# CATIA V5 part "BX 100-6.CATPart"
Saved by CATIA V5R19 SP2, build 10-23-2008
Part number: BX 100-6
Bounding box of the stored display mesh (mm): x -18.951 to 18.951, y -18.952 to 18.952, z 0 to 61
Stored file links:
  C:\Users\Bora\Desktop\3D Katı model\BX serisi\BX 100\BX 100-6.CATPart
  C:\Program Files\Dassault Systemes\B19\intel_a\reffiles\standard\MetricThickPitch.txt
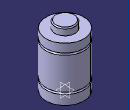
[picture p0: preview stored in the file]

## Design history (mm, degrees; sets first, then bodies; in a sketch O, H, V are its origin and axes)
Body1 (main body)
  Sketch1 on yz-plane, origin (0, 0, 0), H (0, 1, 0), V (0, 0, 1)
    point P1 (19, 45.5)
    line L1 (19, 54) -> (19, 45.5)
    point P4 (10, 60)
    line L2 (10, 60) -> (10, 54)
    point P6 (10, 60)
    arc A1 centre (9, 60) radius 1 from (10, 60) to (9, 61) ccw
    point P7 (19, 43.5)
    point P8 (19, 45.5)
    arc A2 centre (19, 44.5) radius 1 from (19, 45.5) to (19, 43.5) ccw
    point P9 (19, 11.5)
    point P10 (19, 43.5)
    line L3 (19, 43.5) -> (19, 11.5)
    point P11 (19, 9.5)
    point P12 (19, 11.5)
    arc A3 centre (19, 10.5) radius 1 from (19, 11.5) to (19, 9.5) ccw
    point P14 (19, 9.5)
    line L4 (19, 9.5) -> (19, 0)
    line L5 (9, 61) -> (0, 61)
    line L6 (10, 54) -> (19, 54)
    line L7 (19, 0) -> (0, 0)
    tangency: L5 A1
    horizontal: L6 H, L7 H
    coincidence: P1 P8, P4 P6, P7 P10, P9 P12, P11 P14
  Shaft1: profile Sketch1, axis Sketch1.V, angle 360
  Sketch2 on face of Shaft1 from Sketch1.L7, origin (0, 0, 0), H (1, 0, 0), V (0, -1, 0)
    point P1 (9, 0)
    distance P1 V = 9
  Hole1: placed by Sketch2, at (9, 0, 0) direction (0, 0, 1), diameter 4.917, depth 6, threaded "M6", thread diameter 6, thread depth 6, pitch 1
  Sketch3 on face of Shaft1 from Sketch1.L7, origin (0, 0, 0), H (1, 0, 0), V (0, -1, 0)
    point P1 (-9, 0)
    distance P1 V = 9
  Hole2: placed by Sketch3, at (-9, 0, 0) direction (0, 0, 1), diameter 4.917, depth 6, threaded "M6", thread diameter 6, thread depth 6, pitch 1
